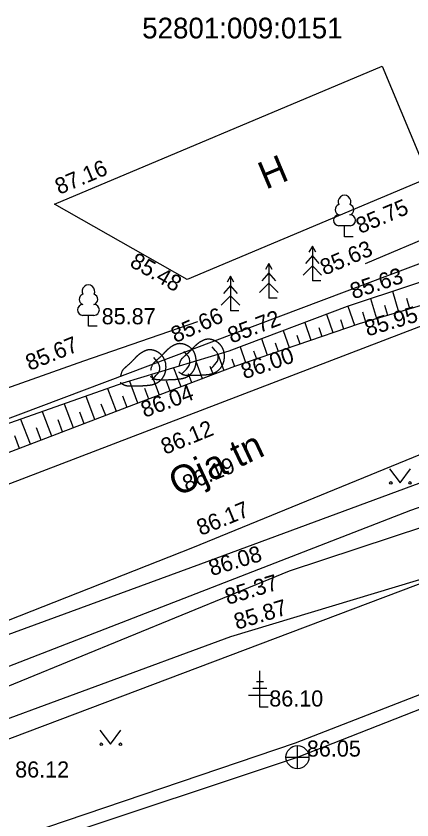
# Model space of a CAD drawing. Extents: x 648748 to 649126, y 6457789 to 6458252.
# Drawn here: x 648916.41 to 648933.59, y 6458118.21 to 6458153.1 of the extents above; entities that cross this region are included whole.
import ezdxf

# ---------------------------------------------------------------- set-up
doc = ezdxf.new("R2010")
doc.units = 0
for name, color, linetype in [('HALJASTUS', 7, 'Continuous'), ('HOONE', 7, 'Continuous'), ('KKAEV', 7, 'Continuous'), ('KORGUS-EH2000', 7, 'Continuous'), ('KTRASS', 7, 'Continuous'), ('PIIR', 7, 'Continuous'), ('PUU', 7, 'Continuous'), ('RELJEEF', 7, 'Continuous'), ('SITRASS', 7, 'Continuous'), ('SKTRASS', 7, 'Continuous'), ('TEE', 7, 'Continuous'), ('VEEKOGU', 7, 'Continuous'), ('VTRASS', 7, 'Continuous')]:
    doc.layers.add(name, color=color, linetype=linetype)

msp = doc.modelspace()

# ---------------------------------------------------------------- linework, layer by layer
at = {"layer": 'HALJASTUS'}
for p, q in [((648932.618, 6458133.439), (648933.081, 6458132.833)), ((648933.081, 6458132.833), (648933.527, 6458133.439)), ((648920.046, 6458122.097), (648920.51, 6458121.49)), ((648920.51, 6458121.49), (648920.955, 6458122.097))]:
    msp.add_line(p, q, dxfattribs=at)
for points in [[(648940.732, 6458145.876), (648934.846, 6458143.735), (648931.564, 6458142.345)], [(648924.28, 6458139.819), (648919.338, 6458138.114), (648909.894, 6458134.773)]]:
    msp.add_lwpolyline(points, dxfattribs=at)
for centre in [(648932.68, 6458132.833), (648933.509, 6458132.833), (648920.109, 6458121.49), (648920.938, 6458121.49)]:
    msp.add_circle(centre, 0.055, dxfattribs=at)
at = {"layer": 'HOONE'}
msp.add_lwpolyline([(648918.081, 6458144.932), (648932.296, 6458150.916), (648934.332, 6458146.079), (648923.834, 6458141.66), (648918.081, 6458144.932)], dxfattribs=at)
at = {"layer": 'KKAEV'}
for p, q in [((648928.625, 6458120.43), (648928.625, 6458121.43)), ((648928.125, 6458120.93), (648929.125, 6458120.93))]:
    msp.add_line(p, q, dxfattribs=at)
msp.add_circle((648928.625, 6458120.93), 0.5, dxfattribs=at)
at = {"layer": 'KTRASS'}
for p, q in [((648928.625, 6458120.93), (648957.262, 6458132.173)), ((648899.409, 6458111.226), (648928.625, 6458120.93))]:
    msp.add_line(p, q, dxfattribs=at)
at = {"layer": 'PIIR'}
for p, q in [((648945.9, 6458146.87), (648892.07, 6458126.56)), ((648895.06, 6458113.79), (648952.09, 6458135.31))]:
    msp.add_line(p, q, dxfattribs=at)
at = {"layer": 'PUU'}
for p, q in [((648930.906, 6458143.996), (648930.426, 6458143.996)), ((648930.666, 6458143.521), (648930.666, 6458143.996)), ((648931.046, 6458143.521), (648930.666, 6458143.521)), ((648929.273, 6458143.102), (648929.123, 6458142.852)), ((648929.423, 6458142.852), (648929.273, 6458143.102)), ((648929.273, 6458143.102), (648929.273, 6458141.602)), ((648929.273, 6458142.702), (648928.973, 6458142.352)), ((648929.573, 6458142.352), (648929.273, 6458142.702)), ((648927.381, 6458142.35), (648927.231, 6458142.1)), ((648927.531, 6458142.1), (648927.381, 6458142.35)), ((648927.381, 6458142.35), (648927.381, 6458140.85)), ((648929.273, 6458142.252), (648928.873, 6458141.852)), ((648929.673, 6458141.852), (648929.273, 6458142.252)), ((648925.719, 6458141.803), (648925.569, 6458141.553)), ((648925.869, 6458141.553), (648925.719, 6458141.803)), ((648925.719, 6458141.803), (648925.719, 6458140.303)), ((648927.381, 6458141.95), (648927.081, 6458141.6)), ((648927.681, 6458141.6), (648927.381, 6458141.95)), ((648927.381, 6458141.5), (648926.981, 6458141.1)), ((648927.781, 6458141.1), (648927.381, 6458141.5)), ((648929.633, 6458141.602), (648929.273, 6458141.602)), ((648925.719, 6458141.403), (648925.419, 6458141.053)), ((648926.019, 6458141.053), (648925.719, 6458141.403)), ((648925.719, 6458140.953), (648925.319, 6458140.553)), ((648926.119, 6458140.553), (648925.719, 6458140.953)), ((648927.741, 6458140.85), (648927.381, 6458140.85)), ((648919.788, 6458140.105), (648919.308, 6458140.105)), ((648919.548, 6458139.63), (648919.548, 6458140.105)), ((648926.079, 6458140.303), (648925.719, 6458140.303)), ((648919.928, 6458139.63), (648919.548, 6458139.63)), ((648926.993, 6458123.105), (648926.993, 6458124.68)), ((648927.143, 6458124.205), (648926.843, 6458124.205)), ((648927.293, 6458123.905), (648926.693, 6458123.905)), ((648927.493, 6458123.605), (648926.493, 6458123.605)), ((648927.353, 6458123.105), (648926.993, 6458123.105))]:
    msp.add_line(p, q, dxfattribs=at)
for centre, radius, start, end in [((648930.666, 6458145.041), 0.277, 332.58, 207.42), ((648930.496, 6458144.694), 0.233, 109.022, 253.142), ((648930.836, 6458144.694), 0.233, 286.851, 70.986), ((648930.429, 6458144.234), 0.238, 90.002, 269.395), ((648930.904, 6458144.234), 0.238, 270.605, 89.998), ((648919.548, 6458141.15), 0.277, 332.58, 207.42), ((648919.378, 6458140.803), 0.233, 109.022, 253.142), ((648919.718, 6458140.803), 0.233, 286.851, 70.986), ((648919.311, 6458140.343), 0.238, 90.002, 269.395), ((648919.786, 6458140.343), 0.238, 270.605, 89.998)]:
    msp.add_arc(centre, radius, start, end, dxfattribs=at)
at = {"layer": 'RELJEEF'}
for p, q in [((648932.748, 6458141.15), (648933.013, 6458140.257)), ((648931.799, 6458140.834), (648932.054, 6458139.973)), ((648933.358, 6458140.854), (648933.492, 6458140.4)), ((648930.815, 6458140.505), (648931.098, 6458139.68)), ((648932.404, 6458140.554), (648932.534, 6458140.115)), ((648929.878, 6458140.153), (648930.153, 6458139.355)), ((648931.45, 6458140.253), (648931.575, 6458139.831)), ((648928.942, 6458139.801), (648929.207, 6458139.03)), ((648930.486, 6458139.923), (648930.626, 6458139.517)), ((648928.006, 6458139.448), (648928.261, 6458138.705)), ((648929.545, 6458139.585), (648929.68, 6458139.192)), ((648927.07, 6458139.095), (648927.315, 6458138.38)), ((648928.604, 6458139.246), (648928.734, 6458138.867)), ((648926.134, 6458138.742), (648926.37, 6458138.055)), ((648927.663, 6458138.907), (648927.788, 6458138.542)), ((648925.166, 6458138.415), (648925.429, 6458137.716)), ((648926.722, 6458138.568), (648926.843, 6458138.217)), ((648924.207, 6458138.124), (648924.493, 6458137.363)), ((648925.771, 6458138.226), (648925.897, 6458137.892)), ((648923.247, 6458137.834), (648923.558, 6458137.011)), ((648924.824, 6458137.905), (648924.961, 6458137.54)), ((648921.329, 6458137.253), (648921.686, 6458136.305)), ((648922.288, 6458137.544), (648922.622, 6458136.658)), ((648922.929, 6458137.262), (648923.09, 6458136.834)), ((648923.876, 6458137.583), (648924.025, 6458137.187)), ((648920.377, 6458136.931), (648920.752, 6458135.95)), ((648921.981, 6458136.94), (648922.154, 6458136.482)), ((648919.433, 6458136.598), (648919.817, 6458135.593)), ((648921.034, 6458136.613), (648921.219, 6458136.128)), ((648918.49, 6458136.266), (648918.883, 6458135.236)), ((648920.095, 6458136.268), (648920.284, 6458135.771)), ((648917.547, 6458135.933), (648917.949, 6458134.88)), ((648919.156, 6458135.923), (648919.35, 6458135.415)), ((648916.603, 6458135.6), (648917.015, 6458134.523)), ((648918.217, 6458135.579), (648918.416, 6458135.058)), ((648917.278, 6458135.234), (648917.482, 6458134.701)), ((648916.34, 6458134.889), (648916.548, 6458134.344))]:
    msp.add_line(p, q, dxfattribs=at)
for points in [[(648891.402, 6458125.263), (648892.278, 6458126.419), (648895.437, 6458127.773), (648900.348, 6458129.598), (648909.816, 6458133.207), (648921.057, 6458137.171), (648925.663, 6458138.565), (648930.796, 6458140.499), (648936.472, 6458142.392), (648941.646, 6458144.685), (648943.957, 6458145.386), (648945.119, 6458145.311)], [(648891.402, 6458125.263), (648895.428, 6458126.406), (648900.776, 6458128.251), (648910.226, 6458131.931), (648921.515, 6458136.241), (648925.907, 6458137.896), (648931.321, 6458139.756), (648936.899, 6458141.409), (648941.788, 6458143.605), (648945.119, 6458145.311)], [(648924.853, 6458137.775), (648924.896, 6458137.82), (648924.964, 6458137.893), (648925.032, 6458137.967), (648925.1, 6458138.041), (648925.156, 6458138.122), (648925.181, 6458138.219), (648925.182, 6458138.319), (648925.161, 6458138.416), (648925.118, 6458138.506), (648925.055, 6458138.584), (648924.99, 6458138.659), (648924.924, 6458138.735)], [(648923.622, 6458137.582), (648923.665, 6458137.627), (648923.733, 6458137.7), (648923.801, 6458137.774), (648923.869, 6458137.848), (648923.925, 6458137.929), (648923.95, 6458138.026), (648923.951, 6458138.126), (648923.93, 6458138.223), (648923.887, 6458138.313), (648923.824, 6458138.391), (648923.759, 6458138.466), (648923.693, 6458138.542)], [(648922.315, 6458137.314), (648922.358, 6458137.359), (648922.426, 6458137.432), (648922.494, 6458137.506), (648922.562, 6458137.58), (648922.618, 6458137.661), (648922.643, 6458137.758), (648922.644, 6458137.858), (648922.623, 6458137.955), (648922.58, 6458138.045), (648922.517, 6458138.123), (648922.452, 6458138.198), (648922.386, 6458138.274)]]:
    msp.add_lwpolyline(points, dxfattribs=at)
for points in [[(648923.468, 6458137.655), (648923.468, 6458137.655), (648923.473, 6458137.647), (648923.667, 6458137.518), (648923.917, 6458137.505), (648924.167, 6458137.505), (648924.417, 6458137.512), (648924.666, 6458137.529), (648924.913, 6458137.564), (648925.139, 6458137.667), (648925.315, 6458137.844), (648925.428, 6458138.065), (648925.463, 6458138.312), (648925.434, 6458138.559), (648925.326, 6458138.783), (648925.146, 6458138.955), (648924.92, 6458139.059), (648924.673, 6458139.079), (648924.442, 6458138.984), (648924.239, 6458138.84), (648924.065, 6458138.661), (648923.892, 6458138.481), (648923.703, 6458138.317), (648923.521, 6458138.148), (648923.477, 6458137.905)], [(648922.237, 6458137.462), (648922.237, 6458137.462), (648922.242, 6458137.454), (648922.436, 6458137.325), (648922.686, 6458137.312), (648922.936, 6458137.312), (648923.186, 6458137.319), (648923.435, 6458137.336), (648923.682, 6458137.371), (648923.908, 6458137.474), (648924.084, 6458137.651), (648924.197, 6458137.872), (648924.232, 6458138.119), (648924.203, 6458138.366), (648924.095, 6458138.59), (648923.915, 6458138.762), (648923.689, 6458138.866), (648923.442, 6458138.886), (648923.211, 6458138.791), (648923.008, 6458138.647), (648922.834, 6458138.468), (648922.661, 6458138.288), (648922.472, 6458138.124), (648922.29, 6458137.955), (648922.246, 6458137.712)], [(648920.93, 6458137.194), (648920.93, 6458137.194), (648920.935, 6458137.186), (648921.129, 6458137.057), (648921.379, 6458137.044), (648921.629, 6458137.044), (648921.879, 6458137.051), (648922.128, 6458137.068), (648922.375, 6458137.103), (648922.601, 6458137.206), (648922.777, 6458137.383), (648922.89, 6458137.604), (648922.925, 6458137.851), (648922.896, 6458138.098), (648922.788, 6458138.322), (648922.608, 6458138.494), (648922.382, 6458138.598), (648922.135, 6458138.618), (648921.904, 6458138.523), (648921.701, 6458138.379), (648921.527, 6458138.2), (648921.354, 6458138.02), (648921.165, 6458137.856), (648920.983, 6458137.687), (648920.939, 6458137.444)]]:
    msp.add_open_spline(points, degree=2, dxfattribs=at)
at = {"layer": 'SITRASS'}
msp.add_lwpolyline([(648863.975, 6458121.708), (648868.963, 6458118.276), (648873.908, 6458114.787), (648879.921, 6458111.046), (648881.11, 6458110.63), (648883.242, 6458110.955), (648895.055, 6458116.596), (648901.713, 6458119.167), (648915.597, 6458124.69), (648933.55, 6458131.654), (648947.17, 6458136.394), (648958.488, 6458140.137), (648967.592, 6458140.769)], dxfattribs=at)
at = {"layer": 'SKTRASS'}
msp.add_lwpolyline([(648864.925, 6458092.31), (648866.693, 6458094.618), (648870.108, 6458099.799), (648873.651, 6458103.509), (648877.881, 6458106.787), (648884.142, 6458110.459), (648889.114, 6458113.182), (648901.758, 6458118.582), (648914.292, 6458123.291), (648928.272, 6458129.024), (648937.137, 6458131.944), (648947.113, 6458135.218)], dxfattribs=at)
at = {"layer": 'TEE'}
for points in [[(648891.319, 6458123.494), (648901.175, 6458127.077), (648933.887, 6458139.607), (648944.575, 6458143.741), (648947.822, 6458145.717), (648948.882, 6458147.636), (648949.478, 6458151.73), (648949.531, 6458156.617), (648950.372, 6458161.859), (648951.909, 6458167.68), (648954.505, 6458172.94), (648956.528, 6458180.218), (648952.525, 6458185.448), (648945.526, 6458192.898), (648938.29, 6458202.321), (648932.248, 6458208.399), (648929.676, 6458210.569), (648928.257, 6458209.969), (648926.047, 6458207.531), (648924.786, 6458206.368), (648922.091, 6458200.973), (648909.112, 6458176.906), (648898.467, 6458156.964), (648883.402, 6458130.595)], [(648964.651, 6458078.174), (648966.451, 6458083.821), (648967.5, 6458089.655), (648970.461, 6458102.422), (648972.022, 6458109.308), (648974.38, 6458121.59), (648976.218, 6458132.059), (648976.233, 6458135.434), (648975.702, 6458138.304), (648974.226, 6458140.713), (648971.86, 6458143.333), (648969.445, 6458145.153), (648966.422, 6458144.919), (648958.871, 6458143.041), (648949.896, 6458140.146), (648946.296, 6458138.815), (648935.488, 6458134.684), (648924.063, 6458130.013), (648903.056, 6458121.74), (648892.363, 6458117.796), (648888.636, 6458116.575), (648879.911, 6458112.582)]]:
    msp.add_lwpolyline(points, dxfattribs=at)
at = {"layer": 'VEEKOGU'}
msp.add_lwpolyline([(648881.501, 6458110.34), (648886.47, 6458113.521), (648891.938, 6458116.388), (648903.218, 6458121.14), (648912.855, 6458125.083), (648924.425, 6458129.317), (648935.909, 6458133.554), (648937.278, 6458129.638), (648925.712, 6458126.147), (648913.923, 6458121.814), (648904.01, 6458118.277), (648893.604, 6458113.65), (648888.243, 6458110.763), (648882.29, 6458107.188)], dxfattribs=at)
at = {"layer": 'VTRASS'}
msp.add_lwpolyline([(648859.612, 6458137.039), (648866.748, 6458133.902), (648887.357, 6458125.656), (648899.553, 6458111.732), (648928.544, 6458121.558), (648956.932, 6458132.595), (648957.558, 6458132.798), (648975.434, 6458138.594), (648975.797, 6458138.798), (648976.302, 6458139.082)], dxfattribs=at)

# ---------------------------------------------------------------- texts
at = {"layer": 'HOONE'}
msp.add_text('H', height=1.2, rotation=22.828, dxfattribs=at).set_placement((648927.252, 6458145.554))
at = {"layer": 'KORGUS-EH2000'}
for s, rotation, p in [('87.16', 22.828, (648918.282, 6458145.335)), ('85.75', 22.828, (648931.346, 6458143.631)), ('85.63', 23.0124, (648929.795, 6458141.825)), ('85.48', 330.3711, (648921.297, 6458142.259)), ('85.63', 18.444, (648931.051, 6458140.797)), ('85.66', 23.8308, (648923.322, 6458138.896)), ('85.95', 16.5068, (648931.665, 6458139.187)), ('85.72', 20.6453, (648925.76, 6458138.879)), ('85.67', 22.1045, (648916.997, 6458137.691)), ('86.00', 18.9604, (648926.32, 6458137.327)), ('86.04', 20.6475, (648921.988, 6458135.652)), ('86.12', 22.2367, (648922.874, 6458134.048)), ('86.19', 22.2367, (648923.811, 6458132.444)), ('86.17', 22.2367, (648924.424, 6458130.53)), ('86.08', 16.7955, (648924.895, 6458128.786)), ('85.37', 16.7955, (648925.597, 6458127.537)), ('85.87', 16.7955, (648925.992, 6458126.456))]:
    msp.add_text(s, height=0.7, rotation=rotation, dxfattribs=at).set_placement(p)
for s, p in [('85.87', (648920.126, 6458139.718)), ('86.10', (648927.4, 6458123.128)), ('86.05', (648929.032, 6458120.953)), ('86.12', (648916.369, 6458120.046))]:
    msp.add_text(s, height=0.7, dxfattribs=at).set_placement(p)
at = {"layer": 'PIIR'}
msp.add_text('52801:009:0151', height=0.9, dxfattribs=at).set_placement((648921.882, 6458152.126))
at = {"layer": 'TEE'}
msp.add_text('Oja tn', height=1.2, rotation=25.2371, dxfattribs=at).set_placement((648923.404, 6458132.223))

doc.saveas('drawing.dxf')
